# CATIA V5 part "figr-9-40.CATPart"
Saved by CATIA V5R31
Part number: Part1
Bounding box of the stored display mesh (mm): x -40 to 40, y -20 to 191.034, z 0 to 131.919
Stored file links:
  D:\PROJECTS\Project 2021\US EDITION\CATIA V5 6R 2021\Resources\Part Files\c09_catia_v5_6r2021_prt\c09_catia_v5_6r2021_prt\figr-9-40.CATPart
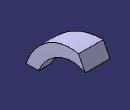
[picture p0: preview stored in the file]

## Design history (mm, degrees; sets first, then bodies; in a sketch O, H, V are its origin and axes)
Set1
  Plane1: type Normal, Curve Sketch2, RefPoint vertex of Sketch2
Body1 (main body)
  Sketch1 on xy-plane, origin (0, 0, 0), H (1, 0, 0), V (0, 1, 0)
    line L1 (20, 20) -> (20, -20)
    line L2 (20, -20) -> (-20, -20)
    line L3 (-20, -20) -> (-20, 20)
    line L4 (-20, 20) -> (20, 20)
    vertical: L1 V, L3 V
    horizontal: L2 H, L4 H
    equidistance: L1 L3 O, L2 L4 O
  Sketch2 on yz-plane, origin (0, 0, 0), H (0, 1, 0), V (0, 0, 1)
    spline S1 through (0, 0) (20, 60) (60, 80) (120, 90) (180, 110)
    point P1 (0, 0)
    coincidence: P1 O
  Sketch3 on Plane1, origin (0, 186.3865, 97.8327), H (1, 0, 0), V (0, -0.4648, 0.8854)
    point P1 (0, 13.7415)
    line L1 (40, 37.4831) -> (40, -10)
    line L2 (40, -10) -> (-40, -10)
    line L3 (-40, -10) -> (-40, 37.4831)
    line L4 (-40, 37.4831) -> (40, 37.4831)
    reference projected point E1 (0, 13.7415) from vertex of Sketch2
    coincidence: P1 V, P1 E1
    vertical: L1 V, L3 V
    horizontal: L2 H, L4 H
    equidistance: L1 L3 P1, L2 L4 P1
  Loft1: Sections (Sketch1; Sketch3)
